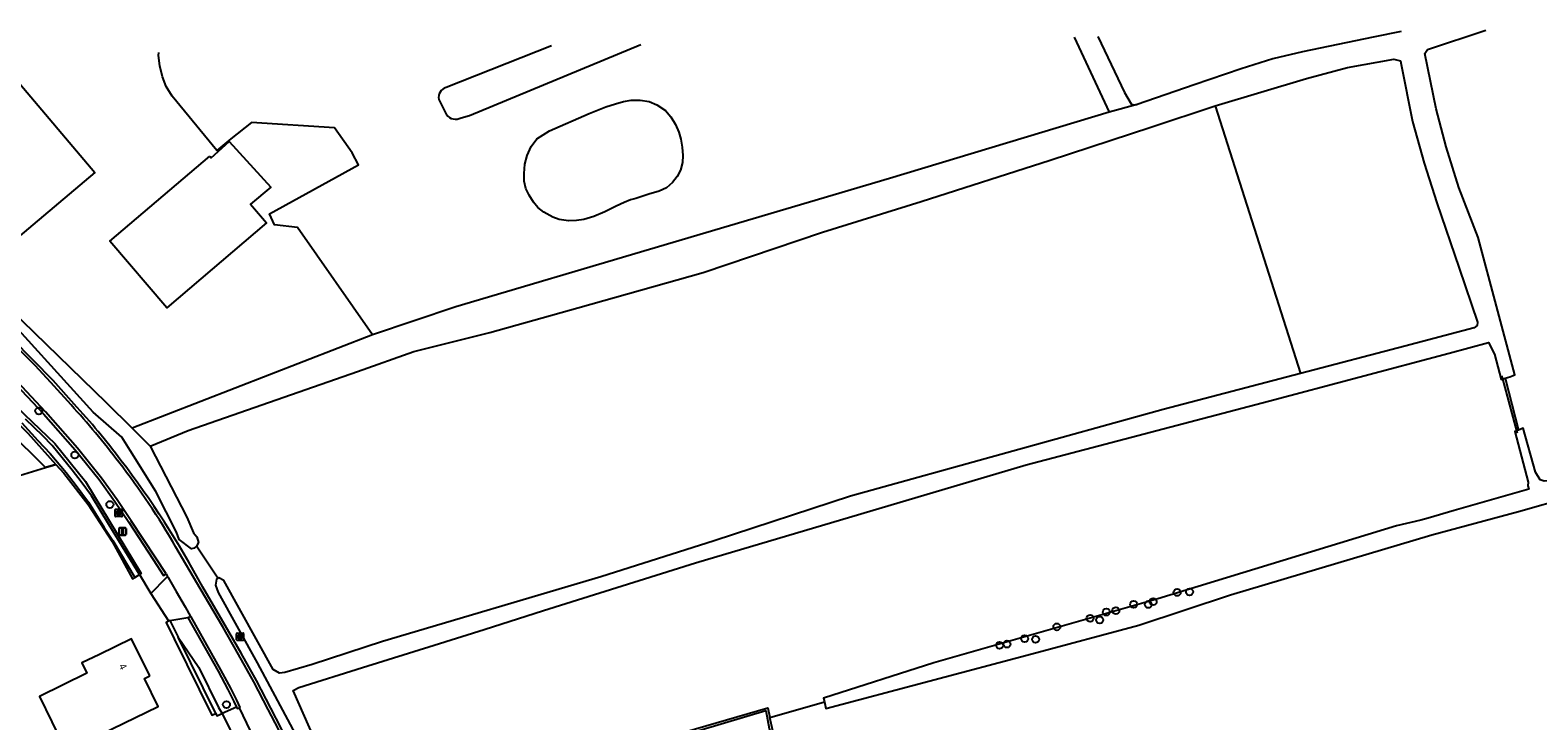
# Model space of a CAD drawing. Extents: x 162515 to 163909, y 388494 to 389773.
# Drawn here: x 163081.8 to 163292.6, y 389671.2 to 389767.8 of the extents above; entities that cross this region are included whole.
import ezdxf

# ---------------------------------------------------------------- set-up
doc = ezdxf.new("R2010")
doc.units = 0
for name, color, linetype in [('IMGEO_Afsluitpaal', 7, 'Continuous'), ('IMGEO_Boom', 7, 'Continuous'), ('IMGEO_Brandkraan', 7, 'Continuous'), ('IMGEO_Duiker', 7, 'Continuous'), ('IMGEO_Erf', 7, 'Continuous'), ('IMGEO_Grasland_agrarisch', 7, 'Continuous'), ('IMGEO_Grasland_overig', 7, 'Continuous'), ('IMGEO_Haag', 7, 'Continuous'), ('IMGEO_Hek', 7, 'Continuous'), ('IMGEO_Loofbos', 7, 'Continuous'), ('IMGEO_Pand', 7, 'Continuous'), ('IMGEO_Pand_nummerreeks', 7, 'Continuous'), ('IMGEO_Rijbaan_lokaal_gesloten', 7, 'Continuous'), ('IMGEO_Rijbaan_lokaal_halfverhard', 7, 'Continuous'), ('IMGEO_Rijbaan_lokaal_open', 7, 'Continuous'), ('IMGEO_Rioolput', 7, 'Continuous'), ('IMGEO_Sloot', 7, 'Continuous'), ('IMGEO_Waterloop', 7, 'Continuous')]:
    doc.layers.add(name, color=color, linetype=linetype)

msp = doc.modelspace()

# ---------------------------------------------------------------- linework, layer by layer
at = {"layer": 'IMGEO_Afsluitpaal'}
for p, q in [((163094.27, 389697.27), (163094.27, 389698.07)), ((163094.27, 389698.07), (163094.27, 389697.27)), ((163094.37, 389698.17), (163095.16, 389698.17)), ((163095.16, 389698.17), (163094.37, 389698.17)), ((163095.16, 389697.17), (163094.37, 389697.17)), ((163094.37, 389697.17), (163095.16, 389697.17)), ((163095.26, 389698.07), (163095.26, 389697.27)), ((163095.26, 389697.27), (163095.26, 389698.07))]:
    msp.add_line(p, q, dxfattribs=at)
msp.add_lwpolyline([(163094.69, 389698.04), (163094.84, 389698.04), (163094.84, 389697.29), (163094.69, 389697.29), (163094.69, 389698.04)], dxfattribs=at)
for centre, start, end in [((163094.37, 389698.07), 90, 180), ((163094.37, 389698.07), 90, 180), ((163094.37, 389697.27), 180, 270), ((163094.37, 389697.27), 180, 270), ((163095.16, 389698.07), 0, 90), ((163095.16, 389698.07), 360, 90), ((163095.16, 389697.27), 270, 0), ((163095.16, 389697.27), 270, 0)]:
    msp.add_arc(centre, 0.1, start, end, dxfattribs=at)
at = {"layer": 'IMGEO_Boom'}
for centre in [(163083.05, 389714.53), (163088.09, 389708.37), (163092.98, 389701.44), (163236.13, 389687.47), (163238.18, 389687.46), (163238.85, 389687.84), (163242.21, 389689.14), (163243.94, 389689.22), (163230.04, 389685.51), (163231.38, 389685.29), (163232.31, 389686.39), (163233.63, 389686.58), (163225.39, 389684.33), (163217.38, 389681.74), (163218.42, 389681.91), (163220.89, 389682.67), (163222.42, 389682.58), (163109.29, 389673.45)]:
    msp.add_circle(centre, 0.489, dxfattribs=at)
at = {"layer": 'IMGEO_Brandkraan'}
for p, q in [((163093.71, 389699.84), (163093.71, 389700.7)), ((163093.78, 389700.77), (163094.64, 389700.77)), ((163094.2, 389700.55), (163094.22, 389700.55)), ((163094.71, 389700.7), (163094.71, 389699.84)), ((163094.64, 389699.77), (163093.78, 389699.77)), ((163094.22, 389699.99), (163094.2, 389699.99))]:
    msp.add_line(p, q, dxfattribs=at)
for points in [[(163093.71, 389699.84), (163093.71, 389700.7)], [(163093.78, 389700.77), (163094.64, 389700.77)], [(163094.06, 389700.47), (163094.06, 389700.07), (163094.27, 389700.07)], [(163094.29, 389700.47), (163094.06, 389700.47)], [(163094.71, 389700.7), (163094.71, 389699.84)], [(163094.64, 389699.77), (163093.78, 389699.77)], [(163094.24, 389700.39), (163094.18, 389700.39), (163094.18, 389700.31)], [(163094.18, 389700.31), (163094.24, 389700.31)], [(163094.25, 389700.24), (163094.18, 389700.24), (163094.18, 389700.15)], [(163094.18, 389700.15), (163094.25, 389700.15)]]:
    msp.add_lwpolyline(points, dxfattribs=at)
for centre, radius, start, end in [((163093.79, 389700.69), 0.0765, 91.552, 178.448), ((163093.79, 389700.69), 0.0765, 91.552, 178.448), ((163094.29, 389700.32), 0.145, 59.4692, 91.5367), ((163094.32, 389700.37), 0.0922, 285.5137, 58.1501), ((163094.63, 389700.69), 0.0765, 1.552, 88.448), ((163094.63, 389700.69), 0.0765, 1.552, 88.448), ((163093.79, 389699.84), 0.0765, 181.552, 268.448), ((163093.79, 389699.84), 0.0765, 181.552, 268.448), ((163094.24, 389700.35), 0.0379, 267.8285, 90.9355), ((163094.25, 389700.2), 0.0404, 269.8759, 90.5077), ((163094.28, 389700.32), 0.251, 268.6676, 293.5347), ((163094.32, 389700.18), 0.105, 301.3115, 78.989), ((163094.63, 389699.84), 0.0765, 271.552, 358.448), ((163094.63, 389699.84), 0.0765, 271.552, 358.448)]:
    msp.add_arc(centre, radius, start, end, dxfattribs=at)
for centre, major_axis, ratio, start_param, end_param in [((163094.2, 389700.27), (-0.387, 0.002), 0.722429, 4.712389, 7.853982), ((163094.22, 389700.27), (-0.39, 0.002), 0.717154, 1.570796, 4.712389)]:
    msp.add_ellipse(centre, major_axis=major_axis, ratio=ratio, start_param=start_param, end_param=end_param, dxfattribs=at)
at = {"layer": 'IMGEO_Duiker'}
msp.add_lwpolyline([(163287.57, 389719.43), (163287.69, 389719), (163289.68, 389711.75), (163289.76, 389711.43)], dxfattribs=at)
at = {"layer": 'IMGEO_Erf'}
for points in [[(163085.44, 389707.04), (163086.53, 389705.83), (163089.93, 389701.45), (163093.29, 389696.28), (163096.13, 389691.04), (163096.48, 389691.25)], [(163107.79, 389672.23), (163107.96, 389671.87), (163108.67, 389672.19)]]:
    msp.add_lwpolyline(points, dxfattribs=at)
at = {"layer": 'IMGEO_Grasland_agrarisch'}
for points in [[(163288.07, 389719.1), (163289.95, 389711.86)], [(163118.81, 389646.87), (163066.29, 389636.03), (163063.36, 389648.6), (163049.05, 389695.77), (163050.19, 389696.14), (163051.31, 389696.5), (163053.35, 389697.16), (163060.78, 389699.57), (163079.14, 389705.13), (163083.99, 389706.6)], [(163185.27, 389671.67), (163192.89, 389673.85)], [(163127.06, 389655.65), (163128.25, 389656.23), (163164.76, 389667.14), (163184.98, 389673), (163185.27, 389671.67)], [(163204.95, 389610.01), (163204.59, 389611.79), (163198.78, 389628.32), (163185.7, 389669.77), (163185.27, 389671.67)]]:
    msp.add_lwpolyline(points, dxfattribs=at)
at = {"layer": 'IMGEO_Grasland_overig'}
for points in [[(163129.7, 389725.19), (163119.24, 389740.19), (163116.01, 389740.57), (163115.29, 389742.12), (163127.73, 389748.96), (163126.86, 389750.62), (163124.39, 389754.15), (163112.8, 389754.86), (163109.9, 389752.61), (163107.92, 389750.97), (163101.7, 389758.54), (163100.86, 389759.93), (163100.34, 389761.29), (163099.99, 389762.8), (163099.8, 389764.24), (163099.82, 389764.68)], [(163042.99, 389750.29), (163043.68, 389750.98), (163044.68, 389750), (163064.38, 389731.06), (163081.07, 389714.04), (163085.27, 389709.98), (163089.56, 389704.66), (163097.34, 389691.77), (163097.11, 389691.63)], [(163083.99, 389706.6), (163041.93, 389748.28)], [(163043.62, 389748.8), (163062.1, 389730.98), (163081.53, 389711.41), (163085.44, 389707.04)], [(163085.44, 389707.04), (163083.99, 389706.6)], [(163097.11, 389691.63), (163098.73, 389688.98)], [(163102.53, 389682.9), (163105.43, 389678.65), (163108.15, 389673.03), (163108.67, 389672.19)]]:
    msp.add_lwpolyline(points, dxfattribs=at)
at = {"layer": 'IMGEO_Haag'}
for points in [[(163101.39, 389685.23), (163100.85, 389684.96), (163101.99, 389682.64), (163107.24, 389671.97), (163107.79, 389672.23)], [(163101.39, 389685.23), (163102.53, 389682.9)], [(163107.79, 389672.23), (163102.53, 389682.9)]]:
    msp.add_lwpolyline(points, dxfattribs=at)
at = {"layer": 'IMGEO_Hek'}
msp.add_lwpolyline([(163050.19, 389696.14), (163051.31, 389696.5), (163053.35, 389697.16), (163060.78, 389699.57), (163079.14, 389705.13), (163083.99, 389706.6), (163085.44, 389707.04)], dxfattribs=at)
at = {"layer": 'IMGEO_Loofbos'}
for points in [[(163247.51, 389757.2), (163259.45, 389719.78)], [(163108.1, 389691.14), (163105.09, 389695.61)]]:
    msp.add_lwpolyline(points, dxfattribs=at)
at = {"layer": 'IMGEO_Pand'}
for points in [[(163076.73, 389758.25), (163079.88, 389760.91), (163090.88, 389747.9), (163080.1, 389738.79), (163059.94, 389762.63), (163061.6, 389764.03)], [(163106.94, 389750.15), (163107.14, 389749.92), (163109.68, 389752.23), (163115.47, 389745.85), (163112.67, 389743.44), (163114.9, 389740.84), (163100.93, 389728.94), (163093, 389738.3), (163106.94, 389750.15)], [(163098.55, 389677.48), (163096.01, 389682.67), (163091.52, 389680.48), (163089.07, 389679.29), (163089.78, 389677.83), (163083.13, 389674.59), (163084.86, 389671.03), (163086.86, 389666.92), (163099.73, 389673.2), (163097.81, 389677.12), (163098.55, 389677.48)]]:
    msp.add_lwpolyline(points, dxfattribs=at)
at = {"layer": 'IMGEO_Rijbaan_lokaal_gesloten'}
for points in [[(163100.84, 389691.74), (163099.39, 389693.96), (163095.98, 389699.17), (163094.02, 389702.1), (163091.83, 389705.15), (163088.44, 389709.34), (163083.99, 389714.39), (163079.4, 389719.3), (163076.61, 389722.17), (163067.71, 389730.69), (163056.54, 389741.42), (163046.2, 389751.36), (163039.32, 389757.98), (163035.76, 389761.38), (163033.47, 389763.56)], [(163087.55, 389715.37), (163084.74, 389718.53), (163082.54, 389720.88), (163076.25, 389727.13), (163074.65, 389728.64)], [(163121.13, 389660.55), (163119.32, 389664.34), (163116.56, 389670), (163115.13, 389672.76), (163113.12, 389676.63), (163110.97, 389680.47), (163108.78, 389684.31), (163105.61, 389689.69), (163102.22, 389695.47)], [(163100.84, 389691.74), (163101.05, 389691.35)], [(163101.05, 389691.35), (163101.12, 389691.21), (163102.25, 389689.27), (163103.52, 389687.12), (163104.28, 389685.76), (163104.31, 389685.72)], [(163104.31, 389685.72), (163108.47, 389678.33), (163109.83, 389675.76), (163110.67, 389674.07), (163111.15, 389673.06), (163111.06, 389673.02)], [(163111.06, 389673.02), (163113.09, 389668.69), (163113.23, 389668.65), (163113.32, 389668.69), (163113.38, 389668.6)]]:
    msp.add_lwpolyline(points, dxfattribs=at)
for centre, radius, start, end in [((163016.69, 389649.66), 96.64, 36.6551, 42.8406), ((163016.2, 389646.21), 99.13, 29.7944, 38.0848)]:
    msp.add_arc(centre, radius, start, end, dxfattribs=at)
at = {"layer": 'IMGEO_Rijbaan_lokaal_halfverhard'}
for points in [[(163038.6, 389758.11), (163039.04, 389757.69), (163045.93, 389751.08), (163056.26, 389741.13), (163067.43, 389730.4), (163076.34, 389721.88), (163079.11, 389719.02), (163083.7, 389714.12), (163088.14, 389709.08), (163091.51, 389704.92), (163093.69, 389701.88), (163095.64, 389698.95), (163099.05, 389693.74), (163100.5, 389691.52), (163100.84, 389691.74)], [(163087.98, 389715.5), (163085.04, 389718.79), (163076.53, 389727.41), (163074.78, 389729.06)], [(163121.49, 389660.72), (163116.92, 389670.18), (163115.49, 389672.95), (163113.47, 389676.83), (163111.32, 389680.67), (163109.12, 389684.51), (163105.96, 389689.9)], [(163103.88, 389685.65), (163108.12, 389678.13), (163109.47, 389675.58), (163110.31, 389673.9), (163110.68, 389673.11)]]:
    msp.add_lwpolyline(points, dxfattribs=at)
for centre, radius, start, end in [((163016.59, 389649.58), 97.17, 36.6639, 42.7185), ((162991.94, 389628.88), 129.32, 28.1533, 37.4998)]:
    msp.add_arc(centre, radius, start, end, dxfattribs=at)
at = {"layer": 'IMGEO_Rijbaan_lokaal_open'}
for points in [[(163101.05, 389691.35), (163100.83, 389691.13), (163098.73, 389688.98)], [(163098.73, 389688.98), (163101.17, 389685.17), (163101.39, 389685.23)], [(163104.31, 389685.72), (163103.88, 389685.65)], [(163101.39, 389685.23), (163103.88, 389685.65)], [(163110.68, 389673.11), (163108.67, 389672.19)], [(163110.68, 389673.11), (163110.79, 389672.89), (163111.06, 389673.02)], [(163108.67, 389672.19), (163110.9, 389667.66), (163111.54, 389666.36), (163111.68, 389666.43)]]:
    msp.add_lwpolyline(points, dxfattribs=at)
at = {"layer": 'IMGEO_Rioolput'}
for p, q in [((163110.69, 389682.52), (163110.69, 389683.37)), ((163110.76, 389683.45), (163111.62, 389683.45)), ((163111.62, 389682.44), (163110.76, 389682.44)), ((163111.18, 389683.22), (163111.2, 389683.22)), ((163111.2, 389682.67), (163111.18, 389682.67)), ((163111.69, 389683.37), (163111.69, 389682.52))]:
    msp.add_line(p, q, dxfattribs=at)
for points in [[(163110.69, 389682.52), (163110.69, 389683.37)], [(163110.76, 389683.45), (163111.62, 389683.45)], [(163111.62, 389682.44), (163110.76, 389682.44)], [(163111.28, 389683.14), (163111.03, 389683.14), (163111.03, 389682.74)], [(163111.03, 389682.74), (163111.15, 389682.74), (163111.15, 389682.91), (163111.16, 389682.91)], [(163111.21, 389683.06), (163111.15, 389683.06), (163111.15, 389682.98)], [(163111.15, 389682.98), (163111.2, 389682.98)], [(163111.21, 389682.88), (163111.28, 389682.74), (163111.42, 389682.74), (163111.35, 389682.87)], [(163111.69, 389683.37), (163111.69, 389682.52)]]:
    msp.add_lwpolyline(points, dxfattribs=at)
for centre, radius, start, end in [((163110.77, 389683.37), 0.0765, 91.552, 178.448), ((163110.77, 389683.37), 0.0765, 91.552, 178.448), ((163110.77, 389682.52), 0.0765, 181.552, 268.448), ((163110.77, 389682.52), 0.0765, 181.552, 268.448), ((163111.16, 389682.85), 0.0533, 26.0293, 88.6989), ((163111.19, 389683.17), 0.19, 274.7715, 282.9687), ((163111.21, 389682.97), 0.0964, 77.0061, 93.1865), ((163111.23, 389683.02), 0.0378, 276.6634, 79.6772), ((163111.28, 389683.03), 0.109, 350.3612, 89.416), ((163111.28, 389683.03), 0.112, 277.5842, 350.9817), ((163111.26, 389682.82), 0.108, 29.5134, 73.7905), ((163111.61, 389683.37), 0.0765, 1.552, 88.448), ((163111.61, 389683.37), 0.0765, 1.552, 88.448), ((163111.61, 389682.52), 0.0765, 271.552, 358.448), ((163111.61, 389682.52), 0.0765, 271.552, 358.448)]:
    msp.add_arc(centre, radius, start, end, dxfattribs=at)
for centre, major_axis, ratio, start_param, end_param in [((163111.18, 389682.94), (-0.387, 0.002), 0.722429, 4.712389, 7.853982), ((163111.2, 389682.94), (-0.39, 0.002), 0.717154, 1.570796, 4.712389)]:
    msp.add_ellipse(centre, major_axis=major_axis, ratio=ratio, start_param=start_param, end_param=end_param, dxfattribs=at)
at = {"layer": 'IMGEO_Sloot'}
for points in [[(163142.09, 389755.53), (163143.28, 389755.87), (163167.23, 389765.81)], [(163227.79, 389766.83), (163232.71, 389756.31)], [(163231.13, 389766.89), (163234.87, 389759.06), (163235.79, 389757.48), (163236.09, 389757.35), (163236.61, 389757.41)], [(163273.52, 389767.6), (163269.63, 389766.82), (163259.74, 389764.76), (163255.57, 389763.78), (163251.17, 389762.38), (163244.61, 389760.16), (163236.61, 389757.41)], [(163288.07, 389719.1), (163288.74, 389719.28), (163289.44, 389719.56), (163284.31, 389738.79), (163281.59, 389745.78), (163279.83, 389751.46), (163278.41, 389756.79), (163276.82, 389764.54), (163277.21, 389765.09), (163285.36, 389767.8)], [(163154.74, 389765.6), (163140, 389759.77)], [(163247.51, 389757.2), (163260.29, 389761.05), (163266.01, 389762.56), (163272.5, 389763.74), (163273.43, 389763.51), (163273.53, 389762.97), (163275.14, 389755.02), (163276.73, 389749.21), (163278.5, 389743.65), (163281.62, 389734.49), (163284.2, 389726.96), (163284.14, 389726.49), (163283.76, 389726.16), (163274.05, 389723.61), (163259.45, 389719.78)], [(163138.96, 389758.1), (163140.05, 389755.97)], [(163169.44, 389757.36), (163170.66, 389756.57), (163171.41, 389755.67), (163172.09, 389754.6), (163172.55, 389753.51), (163172.82, 389752.56), (163173.02, 389751.41), (163173.1, 389750.27), (163173.03, 389749.28), (163172.76, 389748.21), (163172.28, 389747.32), (163171.64, 389746.48), (163170.8, 389745.74), (163169.79, 389745.27), (163168.35, 389744.84), (163166.54, 389744.24), (163165.8, 389744.04), (163164.88, 389743.67), (163163.77, 389743.18), (163162.21, 389742.38), (163160.63, 389741.73), (163159.26, 389741.33), (163158.22, 389741.17), (163157.09, 389741.13), (163155.81, 389741.31), (163154.91, 389741.65), (163153.66, 389742.32), (163152.8, 389743.01), (163152.23, 389743.74), (163151.61, 389744.7), (163151.15, 389745.66), (163150.92, 389746.68), (163150.9, 389747.74), (163151.02, 389749.03), (163151.31, 389750.28), (163151.87, 389751.5), (163152.66, 389752.61), (163154.45, 389753.73), (163159.98, 389756.16), (163162.33, 389757.05), (163163.67, 389757.51), (163164.81, 389757.81), (163165.89, 389758), (163167.14, 389758.02), (163168.38, 389757.81), (163169.44, 389757.36)], [(163236.61, 389757.41), (163232.71, 389756.31)], [(163098.61, 389709.59), (163103.91, 389711.81), (163127.61, 389720.05), (163135.48, 389722.83), (163146.11, 389725.52), (163158.42, 389728.94), (163175.95, 389733.92), (163192.61, 389739.52), (163206.42, 389743.82), (163224.46, 389749.6), (163238.52, 389754.23), (163247.51, 389757.2)], [(163232.71, 389756.31), (163201.99, 389747.04), (163168.42, 389737.11), (163141.35, 389729.09), (163129.7, 389725.19)], [(163129.7, 389725.19), (163096.12, 389712.1)], [(163123.95, 389662.66), (163122.28, 389667.1), (163118.6, 389675.44), (163119.39, 389675.84), (163128.29, 389678.66), (163138.31, 389681.76), (163145.34, 389683.97), (163153.6, 389686.6), (163174.85, 389693.27), (163221.12, 389707.01), (163255, 389715.89), (163280.24, 389722.61), (163285.76, 389724.09), (163286.57, 389722.49), (163287.5, 389718.95), (163287.69, 389719), (163287.81, 389719.03), (163288.07, 389719.1)], [(163259.45, 389719.78), (163240.24, 389714.74), (163196.56, 389702.6), (163177.48, 389696.34), (163161.64, 389691.33), (163131.11, 389682.28), (163121.25, 389679.04), (163117.45, 389677.93), (163116.72, 389677.86), (163115.83, 389678.38), (163108.91, 389690.83), (163108.23, 389691.19), (163108.1, 389691.14)], [(163096.12, 389712.1), (163098.61, 389709.59)], [(163108.1, 389691.14), (163107.87, 389691.02), (163107.76, 389690.16), (163108.13, 389689.14), (163113.58, 389679.31), (163122.8, 389662.04), (163123.23, 389661.71), (163123.61, 389661.72), (163124.04, 389662.03), (163123.95, 389662.66)]]:
    msp.add_lwpolyline(points, dxfattribs=at)
for centre, radius, start, end in [((163140.41, 389758.36), 1.47, 106.0897, 190.1276), ((163141.33, 389756.94), 1.6, 216.9454, 298.3663)]:
    msp.add_arc(centre, radius, start, end, dxfattribs=at)
at = {"layer": 'IMGEO_Waterloop'}
for points in [[(163076.55, 389729.85), (163076.91, 389730.11), (163077.31, 389730.41), (163092.48, 389715.73), (163096.12, 389712.1)], [(163105.09, 389695.61), (163104.76, 389695.34), (163104.38, 389695.26), (163102.66, 389696.57), (163102.32, 389697.57), (163099.41, 389703.24), (163095.83, 389708.99), (163094.66, 389710.87), (163090.67, 389714.38), (163076.55, 389729.85)], [(163097.11, 389691.63), (163095.14, 389694.9), (163092.83, 389698.63), (163090.4, 389702.64), (163088.99, 389704.63), (163087.73, 389706.24), (163084.93, 389709.69), (163083.59, 389711.03), (163081.19, 389713.38)], [(163080.66, 389712.85), (163082.93, 389710.39), (163084.64, 389708.56), (163086.86, 389705.93), (163088.26, 389704.08), (163090, 389701.76), (163092.19, 389698.24), (163093.38, 389696.4), (163096.48, 389691.25)], [(163289.95, 389711.86), (163289.68, 389711.75), (163289.43, 389711.65), (163291.29, 389704.58), (163291.22, 389704.07), (163291.39, 389703.59), (163280.93, 389700.59), (163277.3, 389699.54), (163276.3, 389699.27), (163272.86, 389698.48), (163239.53, 389688.27), (163208.18, 389679.31), (163192.77, 389674.36), (163192.89, 389673.85)], [(163305.91, 389700.45), (163300.79, 389704.34), (163299.85, 389704.77), (163293.53, 389704.71), (163292.99, 389704.91), (163292.33, 389705.96), (163290.6, 389712.12), (163289.95, 389711.86)], [(163098.61, 389709.59), (163103.73, 389699.69), (163104.68, 389697.49), (163105.15, 389696.93), (163105.37, 389696.14), (163105.09, 389695.61)], [(163192.89, 389673.85), (163192.99, 389673.37), (163193.11, 389672.91), (163221.91, 389680.54), (163236.87, 389684.56), (163249.69, 389688.83), (163262.01, 389692.5), (163277.82, 389697.22), (163289.96, 389700.48), (163297.17, 389702.51), (163299.58, 389701.54), (163301.73, 389700.56), (163306.81, 389697.62), (163311.17, 389693.6), (163315.9, 389688.45), (163318.61, 389684.85), (163320.56, 389681.76), (163322.16, 389678.87), (163323.63, 389675.56)], [(163096.48, 389691.25), (163097.11, 389691.63)], [(163127.36, 389654.81), (163127.42, 389654.95), (163127.49, 389655.1), (163128.65, 389655.68), (163141.2, 389659.58), (163157.51, 389664.5), (163184.71, 389672.63), (163185.18, 389670.12), (163186.36, 389666.11), (163190.93, 389652.11), (163195.7, 389637.16), (163203.77, 389611.71), (163205.31, 389601.98), (163207.46, 389588.09), (163208.42, 389584.17), (163209.29, 389580.64), (163210.38, 389576.22), (163210.35, 389576.08), (163210.31, 389575.95)]]:
    msp.add_lwpolyline(points, dxfattribs=at)

# ---------------------------------------------------------------- texts
at = {"layer": 'IMGEO_Pand_nummerreeks'}
msp.add_text('4', height=1, rotation=296.0063, dxfattribs=at).set_placement((163094.21, 389678.89))

doc.saveas('drawing.dxf')
